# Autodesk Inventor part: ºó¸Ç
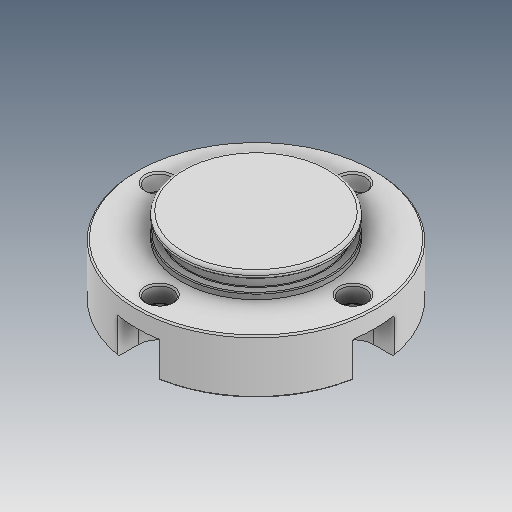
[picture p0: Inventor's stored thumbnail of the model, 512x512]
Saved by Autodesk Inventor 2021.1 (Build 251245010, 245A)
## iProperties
Created: 2014-12
Part Number: ºó¸Ç
Material: Ogólny
Document SubType Name: Modeling
Designer: user
Density: 1 g/cm^3
Appearance: Domyślna
Author: user
Revision Number: ÈÎºÎ
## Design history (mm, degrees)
feature "ÊäÈë1"
node "Bryła1"
